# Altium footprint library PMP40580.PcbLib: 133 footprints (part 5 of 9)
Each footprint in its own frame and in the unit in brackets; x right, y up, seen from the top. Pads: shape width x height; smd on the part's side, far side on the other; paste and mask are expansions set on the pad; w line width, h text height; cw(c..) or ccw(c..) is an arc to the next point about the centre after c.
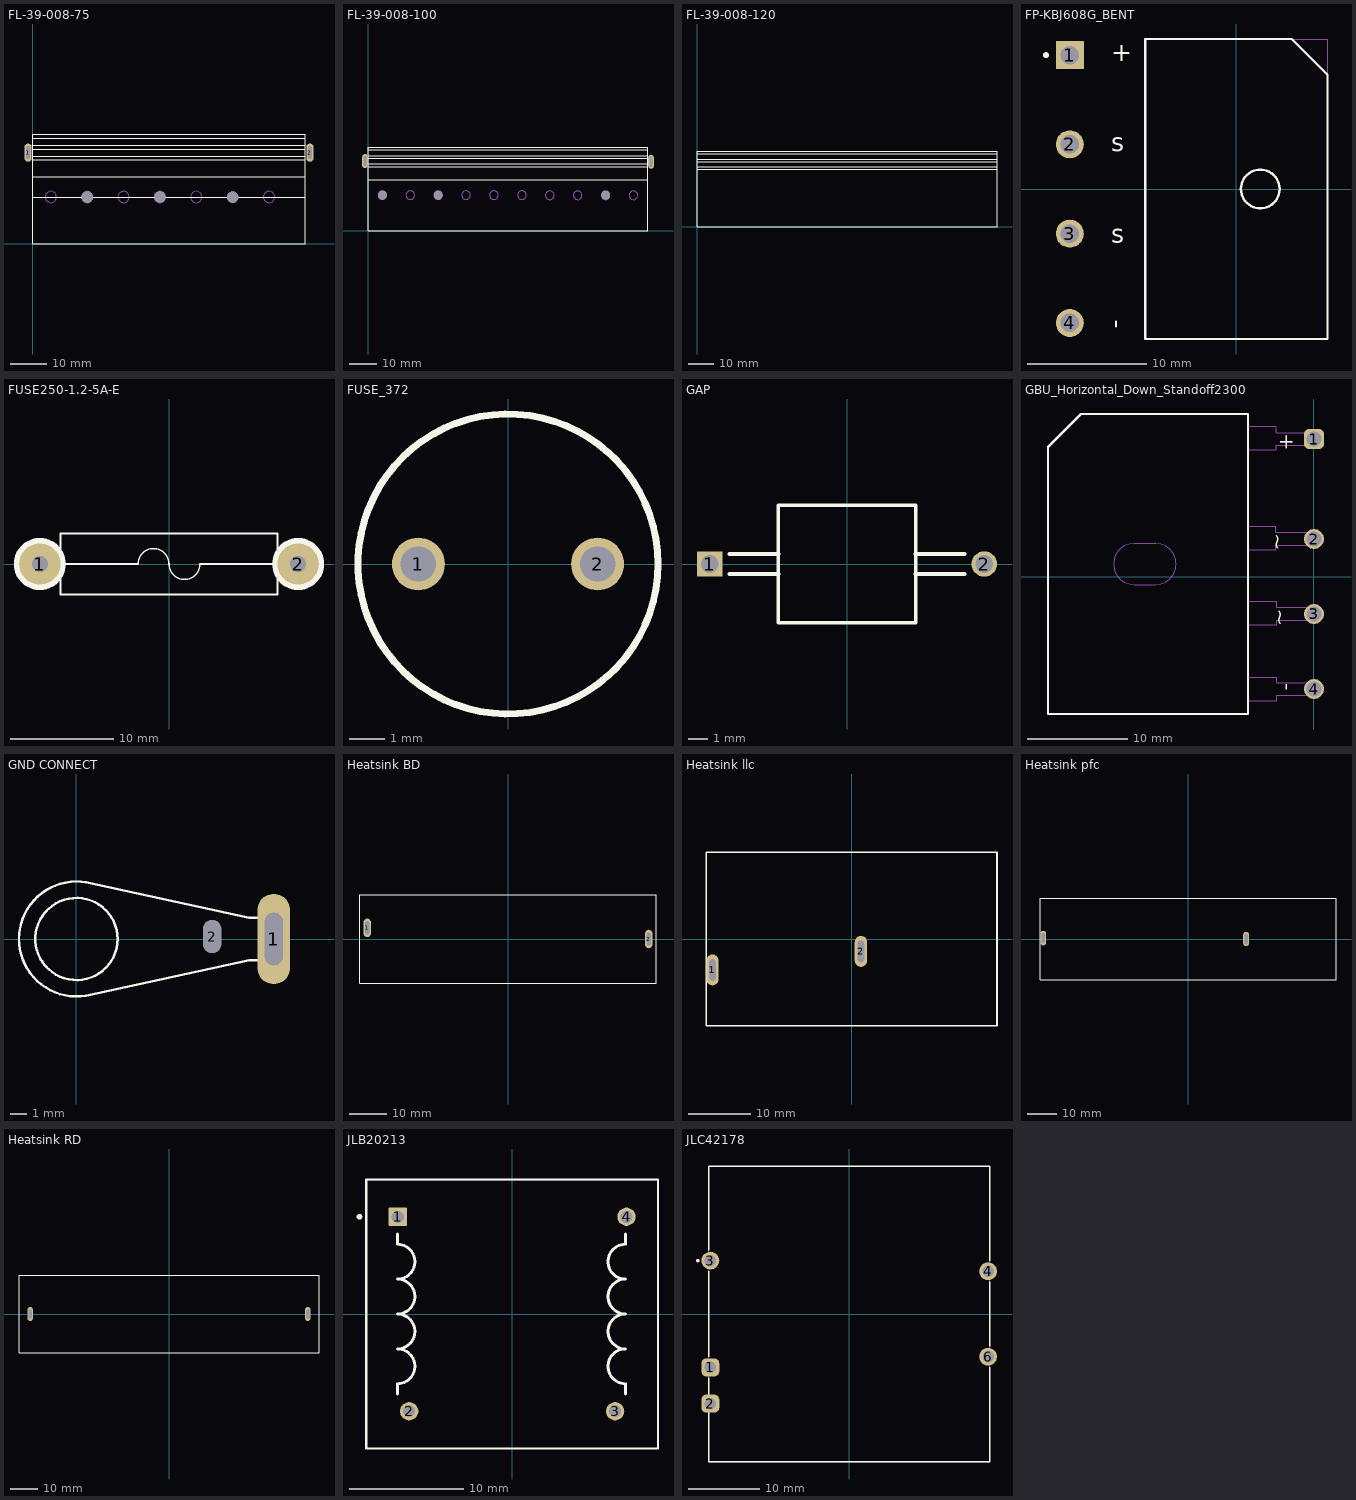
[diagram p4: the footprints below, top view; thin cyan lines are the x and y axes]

## FL-39-008-75 [mm]
pads (5):
  oval 2x5 hole 1 slot 3.5 at 90 deg: 1(-1.25,25) 2(76.25,25)
  round 3.1 hole 3.1: ""(15,12.75) ""(35,12.8) ""(55,12.75)
Top Overlay:
  lines w0.2: 0,12.8 75,12.8 ; 0,18.4 75,18.4 ; 0,23 75,23 ; 0,24 75,24 ; 0,26 75,26 ; 0,27 75,27 ; 0,29 75,29 ; 0,0 75,0 75,30 0,30 0,0
Mechanical 5:
  circle w0.1: c35,12.8 r1.55
  circle w0.1: c15,12.8 r1.55
  circle w0.1: c65,12.8 r1.55
  circle w0.1: c5,12.8 r1.55
  circle w0.1: c25,12.8 r1.55
  circle w0.1: c45,12.8 r1.55

## FL-39-008-100 [mm]
pads (5):
  oval 2x5 hole 1 slot 3.5 at 90 deg: 1(-1.25,25) 2(101.25,24.75)
  round 3.1 hole 3.1: ""(5,12.8) ""(25,12.8) ""(85,12.8)
Top Overlay:
  lines w0.2: 0,18.4 100,18.4 ; 0,23 100,23 ; 0,24 100,24 ; 0,26 100,26 ; 0,27 100,27 ; 0,29 100,29 ; 0,0 100,0 100,30 0,30 0,0
Mechanical 5:
  circle w0.1: c94.975,12.748 r1.55
  circle w0.1: c74.975,12.748 r1.55
  circle w0.1: c84.975,12.748 r1.55
  circle w0.1: c64.975,12.748 r1.55
  circle w0.1: c54.975,12.8 r1.55
  circle w0.1: c44.975,12.8 r1.55
  circle w0.1: c34.975,12.8 r1.55
  circle w0.1: c24.975,12.8 r1.55
  circle w0.1: c14.975,12.8 r1.55
  circle w0.1: c4.975,12.8 r1.55

## FL-39-008-120 [mm]
Top Overlay:
  lines w0.127: 0,23 120,23 ; 0,24 120,24 ; 0,26 120,26 ; 0,27 120,27 ; 0,29 120,29 ; 0,0 0,30 120,30 120,0 0,0

## FP-KBJ608G_BENT [mm]
pads (4):
  rrect4% 2.35x2.35 hole 1.55 paste-1000 mask+0: 1(-14,11.25)
  round 2.35 hole 1.55 paste-1000 mask+0: 2(-14,3.75) 3(-14,-3.75) 4(-14,-11.25)
Top Overlay:
  circle w0.25: c-16,11.25 r0.125
  circle w0.2: c2,0 r1.625
  lines w0.2: -7.65,-12.6 7.65,-12.6 7.65,9.6 4.65,12.6 -7.65,12.6 -7.65,-12.6
  text "+" at -10.5,10.75 h1.52
  text "s" at -10.5,3.175 h1.52
  text "s" at -10.5,-4.5 h1.52
  text "-" at -9.5,-11.75 h1.52
Mechanical 5:
  lines w0.1: -7.65,-12.6 7.65,-12.6 7.65,12.6 -7.65,12.6 -7.65,-12.6
  text ".Designator" at -0.127,0 h0.5
3D body "Diode_KBJ608G_KBJ_Right_Anglev2.stp": height 4.8, standoff -2.3, extent -14.477,-12.5 7.373,12.5

## FP-KBJ608G_KBJ-MFG [mm]

## FUSE250-1.2-5A-E [mm]
pads (2):
  round 4 hole 1.55: 1(-12.5,0) 2(12.5,0)
Top Overlay:
  circle w1: c-12.5,0 r2.016
  circle w1: c12.5,0 r2.016
  lines w0.15: -12.5,0 -3,0 cw(c-1.5,0) 0,0 ccw(c1.5,0) 3,0 12.5,0 ; -10.5,-2.95 -10.5,2.95 10.5,2.95 10.5,-2.95 -10.5,-2.95

## FUSE_372 [mm] "LITTELFUSE"
height 8
pads (2):
  round 1.5 hole 1: 1(-2.54,0) 2(2.54,0)
Top Overlay:
  circle w0.2: c0,0 r4.25
Mechanical 5:
  circle w0.1: c0,0 r4.25
  text ".Designator" at -1.524,-0.508 h1.02
3D body: height 4, standoff -2, extent -2.837,-0.299 -2.24,0.3
3D body: height 4, standoff -2, extent 2.242,-0.299 2.84,0.299
3D body: height 8, standoff 0, extent -4.249,-4.249 4.249,4.249

## GAP [mm] "Vishay dimensions"
height 5.5
pads (2):
  rect 1.3x1.3 hole 0.9: 1(-7,0)
  round 1.3 hole 0.9: 2(7,0)
Top Overlay:
  lines w0.178: -3.5,-3 3.5,-3 3.5,3 -3.5,3 -3.5,-3
  lines w0.2: -6,-0.5 -3.5,-0.5 ; -6,0.5 -3.5,0.5 ; 3.5,-0.5 6,-0.5 ; 3.5,0.5 6,0.5
Mechanical 5:
  lines w0.127: -3.5,2.7 -3.5,-3 3.5,-3 3.5,3 -3.5,3
  text ".Designator" at -0.8,-0.2 h0.51

## GBU_Horizontal_Down_Standoff2300 [mm] "TH, 4-Leads, Body 22.3x18.8mm, Pitch 5.08"
height 5.86
pads (4):
  rrect50% 2x2 hole 1.5: 1(0,13.75)
  round 2 hole 1.5: 2(0,3.75) 3(0,-3.75) 4(0,-11.25)
Top Overlay:
  lines w0.2: -26.6,-13.75 -6.6,-13.75 -6.6,16.25 -23.3,16.25 -26.6,12.95 -26.6,-13.75
  text "~" at -4.075,-3.225 h1.52
  text "~" at -4.325,4.325 h1.52
  text "-" at -3.325,-10.7 h1.52
  text "+" at -3.35,14.35 h1.52
Mechanical 5:
  lines w0.1: -17,3.3 -16.9,3.3 ; -6.6,2.7 -3.85,2.7 -3.85,3.144 -0.82,3.144 0.18,3.144 0.18,4.414 -0.82,4.414 -3.85,4.414 -3.85,5.05 -6.6,5.05 ; -6.5,-4.8 -3.75,-4.8 -3.75,-4.356 -0.72,-4.356 0.28,-4.356 0.28,-3.086 -0.72,-3.086 -3.75,-3.086 -3.75,-2.45 -6.5,-2.45 ; -6.5,12.675 -3.75,12.675 -3.75,13.119 -0.72,13.119 0.28,13.119 0.28,14.389 -0.72,14.389 -3.75,14.389 -3.75,15.025 -6.5,15.025 ; -6.48,-12.415 -3.73,-12.415 -3.73,-11.875 -0.7,-11.875 0.3,-11.875 0.3,-10.605 -0.7,-10.605 -3.73,-10.605 -3.73,-10.065 -6.48,-10.065 ; -26.6,-13.75 -6.6,-13.75 -6.6,16.25 -23.3,16.25 -26.6,12.95 -26.6,-13.75 ; -18,-0.8 cw(c-18,1.25) -18,3.3 -15.84,3.3 cw(c-15.84,1.25) -15.84,-0.8 -18,-0.8
  text ".Designator" at -8.64,-8.25 h1.85
3D body "GBU_Horizontal_Down_Standoff2300.stp": height 5.86, standoff -3.14, extent -25.3,-11.15 0.095,11.15

## GND CONNECT [mm] "GND CONNECT"
height 3.76
pads (2):
  oval 2x5.5 hole 1.1 slot 3.2 at 90 deg: 1(12,0)
  oval 1.1x2 hole 1.1 slot 2 at 90 deg: 2(8.25,0.15)
Top Overlay:
  circle w0.15: c0,0 r2.5
  lines w0.15: 0.575,-3.45 10.5,-1.3 12,-1.3 12,1.3 10.5,1.3 0.575,3.45 ; 0.575,-3.449 cw(c0,0) 0.6,3.445
Mechanical 5:
  text ".Designator" at -2,-1.3 h1.02

## Heatsink BD [mm] "Heat sink,"
height 3.76
pads (2):
  oval 2x5 hole 1 slot 3.5 at 90 deg: 1(-38,3) 2(38,0)
Top Overlay:
  lines w0.254: -40,-12 -40,12 40,12 40,-12 -40,-12
Mechanical 5:
  text ".Designator" at -2,-1.3 h1.02

## Heatsink llc [mm] "Heat sink,"
height 3.76
pads (2):
  oval 2x5 hole 1 slot 3.5 at 90 deg: 1(-22.5,-5) 2(1.5,-2)
Top Overlay:
  lines w0.254: -23.5,-14 23.5,-14 23.5,14 -23.5,14 -23.5,-14
Mechanical 5:
  text ".Designator" at -2,-1.3 h1.02

## Heatsink pfc [mm] "Heat sink,"
height 3.76
pads (2):
  oval 2x5 hole 1 slot 3.5 at 90 deg: 1(-50,0.3) 2(20,0)
Top Overlay:
  lines w0.254: -51,-14 51,-14 51,14 -51,14 -51,-14
Mechanical 5:
  text ".Designator" at -2,-1.3 h1.02

## Heatsink RD [mm] "Heat sink,"
height 3.76
pads (2):
  oval 2x5 hole 1 slot 3.5 at 90 deg: 1(-50,0) 2(50,0)
Top Overlay:
  lines w0.254: -54,-14 -54,14 54,14 54,-14 -54,-14
Mechanical 5:
  text ".Designator" at -2,-1.3 h1.02

## JLB20213 [mm]
pads (4):
  rrect6% 1.6x1.6 hole 1.05 paste-1000 mask+0: 1(-10,8.5)
  round 1.6 hole 1.05 paste-1000 mask+0: 2(-9,-8.5) 3(9,-8.5) 4(10,8.5)
Top Overlay:
  circle w0.25: c-13.35,8.5 r0.125
  lines w0.2: -12.75,-11.75 -12.75,11.75 12.75,11.75 12.75,-11.75 -12.75,-11.75
  lines w0.254: -10.033,-6.985 -10.033,-6.096 ccw(c-10.03,-4.572) -10.033,-3.048 ccw(c-10.03,-1.524) -10.033,0 ccw(c-10.03,1.524) -10.033,3.048 ccw(c-10.03,4.572) -10.033,6.096 -10.033,6.985 ; 9.906,-6.985 9.906,-6.096 cw(c9.903,-4.572) 9.906,-3.048 cw(c9.903,-1.524) 9.906,0 cw(c9.903,1.524) 9.906,3.048 cw(c9.903,4.572) 9.906,6.096 9.906,6.985
Bottom Overlay:
  lines w0.254: -10.033,-6.985 -10.033,-6.096 ccw(c-10.03,-4.572) -10.033,-3.048 ccw(c-10.03,-1.524) -10.033,0 ccw(c-10.03,1.524) -10.033,3.048 ccw(c-10.03,4.572) -10.033,6.096 -10.033,6.985 ; 9.906,-6.985 9.906,-6.096 cw(c9.903,-4.572) 9.906,-3.048 cw(c9.903,-1.524) 9.906,0 cw(c9.903,1.524) 9.906,3.048 cw(c9.903,4.572) 9.906,6.096 9.906,6.985
Mechanical 5:
  lines w0.1: -12.75,-11.75 -12.75,11.75 12.75,11.75 12.75,-11.75 -12.75,-11.75
  text ".Designator" at 0,0 h0.5
3D body "Ind_JLB20213_PTH_23MM5_21MM5.STEP": height 0.25, standoff 0, extent -12.85,-11.85 12.85,11.85

## JLC42178 [mm]
pads (5):
  rrect50% 2.5x2.5 hole 1.6 paste-1000 mask+0: 1(-19.5,-7.5) 2(-19.5,-12.58)
  round 2.5 hole 1.6 paste-1000 mask+0: 3(-19.5,7.5) 4(19.5,6) 6(19.5,-6)
Top Overlay:
  circle w0.25: c-21.25,7.5 r0.125
  lines w0.2: -19.75,-8.975 -19.75,-20.75 19.75,-20.75 19.75,-7.475 ; -19.75,-6.025 -19.75,6.025 ; -19.75,8.975 -19.75,20.75 19.75,20.75 19.75,7.475 ; 19.75,-4.525 19.75,4.525
Mechanical 5:
  lines w0.1: -19.75,-20.75 -19.75,20.75 19.75,20.75 19.75,-20.75 -19.75,-20.75
  text ".Designator" at 0,0 h0.5
3D body "Ind_JLC42178_PTH_IND_39MM0_39MM5.STEP": height 0.25, standoff 0, extent -20.7,-20.85 20.7,20.85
